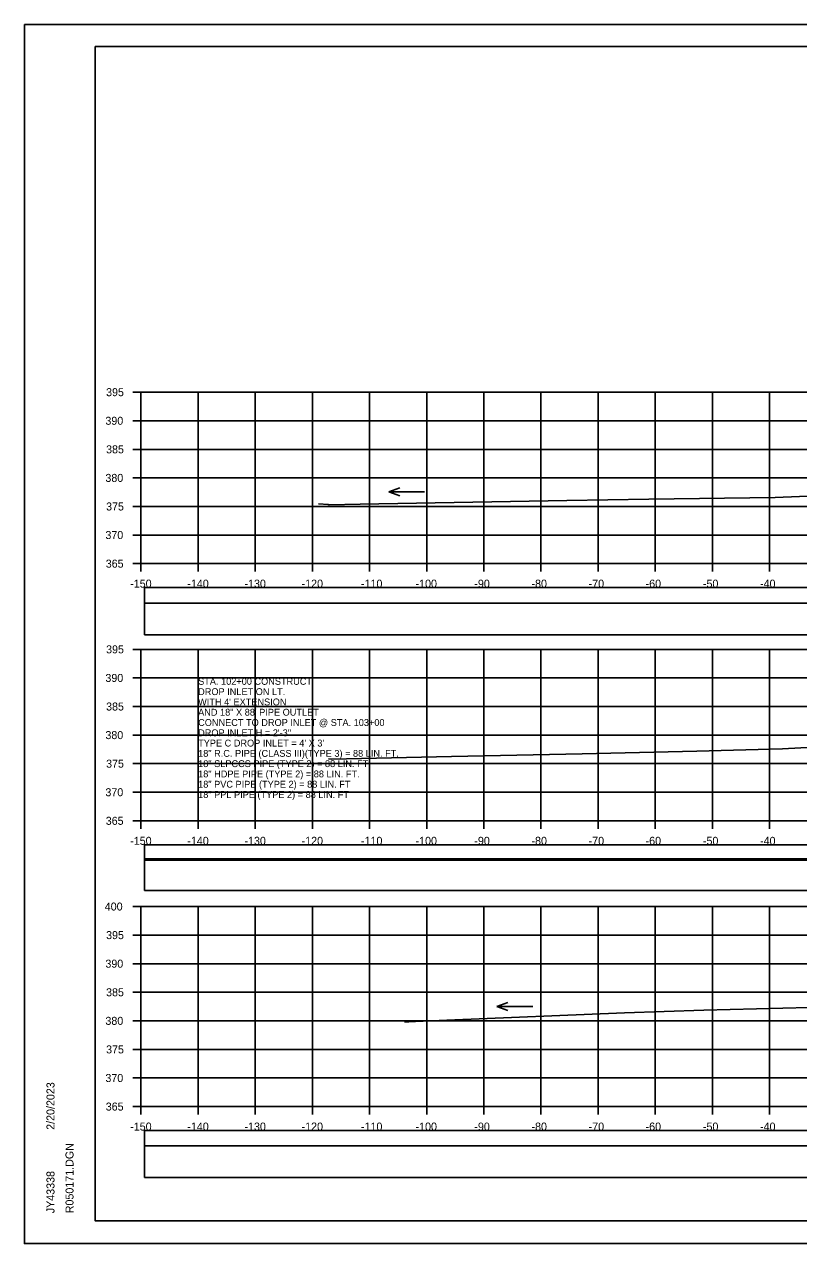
# Model space of a CAD drawing. Extents: x -37291014 to -37290680, y -936053 to -933067.
# Drawn here: x -37291013.5 to -37290878, y -935626.6 to -935413.3 of the extents above; entities that cross this region are included whole.
import ezdxf

# ---------------------------------------------------------------- set-up
doc = ezdxf.new("R2010")
doc.units = 0
for name, color, linetype in [('Default', 7, 'Continuous'), ('R_Axis', 7, 'Continuous'), ('R_Axis Annot', 7, 'Continuous'), ('R_Border', 7, 'Continuous'), ('R_Exist Surface', 7, 'Continuous'), ('R_Grid', 7, 'Continuous'), ('R_No Plot', 7, 'Continuous'), ('R_Water Annot', 7, 'Continuous')]:
    doc.layers.add(name, color=color, linetype=linetype)

msp = doc.modelspace()

# ---------------------------------------------------------------- linework, layer by layer
at = {"layer": 'Default'}
for points in [[(-37290992.48, -935514.55), (-37290693.72, -935514.55), (-37290693.72, -935511.85), (-37290992.48, -935511.85)], [(-37290992.48, -935520.08), (-37290693.72, -935520.08), (-37290693.72, -935514.55), (-37290992.48, -935514.55)], [(-37290992.48, -935559.55), (-37290693.72, -935559.55), (-37290693.72, -935556.85), (-37290992.48, -935556.85)], [(-37290992.48, -935564.82), (-37290693.72, -935564.82), (-37290693.72, -935559.3), (-37290992.48, -935559.3)], [(-37290992.48, -935609.55), (-37290693.72, -935609.55), (-37290693.72, -935606.85), (-37290992.48, -935606.85)], [(-37290992.48, -935615.08), (-37290693.72, -935615.08), (-37290693.72, -935609.55), (-37290992.48, -935609.55)]]:
    msp.add_lwpolyline(points, close=True, dxfattribs=at)
at = {"layer": 'R_Axis'}
for p, q in [((-37290994.5, -935477.65), (-37290993.1, -935477.65)), ((-37290993.1, -935507.65), (-37290993.1, -935477.65)), ((-37290994.5, -935482.65), (-37290993.1, -935482.65)), ((-37290994.5, -935487.65), (-37290993.1, -935487.65)), ((-37290994.5, -935492.65), (-37290993.1, -935492.65)), ((-37290994.5, -935497.65), (-37290993.1, -935497.65)), ((-37290994.5, -935502.65), (-37290993.1, -935502.65)), ((-37290994.5, -935507.65), (-37290993.1, -935507.65)), ((-37290993.1, -935507.65), (-37290693.1, -935507.65)), ((-37290993.1, -935509.05), (-37290993.1, -935507.65)), ((-37290983.1, -935509.05), (-37290983.1, -935507.65)), ((-37290973.1, -935509.05), (-37290973.1, -935507.65)), ((-37290963.1, -935509.05), (-37290963.1, -935507.65)), ((-37290953.1, -935509.05), (-37290953.1, -935507.65)), ((-37290943.1, -935509.05), (-37290943.1, -935507.65)), ((-37290933.1, -935509.05), (-37290933.1, -935507.65)), ((-37290923.1, -935509.05), (-37290923.1, -935507.65)), ((-37290913.1, -935509.05), (-37290913.1, -935507.65)), ((-37290903.1, -935509.05), (-37290903.1, -935507.65)), ((-37290893.1, -935509.05), (-37290893.1, -935507.65)), ((-37290883.1, -935509.05), (-37290883.1, -935507.65)), ((-37290994.5, -935522.65), (-37290993.1, -935522.65)), ((-37290993.1, -935552.65), (-37290993.1, -935522.65)), ((-37290994.5, -935527.65), (-37290993.1, -935527.65)), ((-37290994.5, -935532.65), (-37290993.1, -935532.65)), ((-37290994.5, -935537.65), (-37290993.1, -935537.65)), ((-37290994.5, -935542.65), (-37290993.1, -935542.65)), ((-37290994.5, -935547.65), (-37290993.1, -935547.65)), ((-37290994.5, -935552.65), (-37290993.1, -935552.65)), ((-37290993.1, -935552.65), (-37290693.1, -935552.65)), ((-37290993.1, -935554.05), (-37290993.1, -935552.65)), ((-37290983.1, -935554.05), (-37290983.1, -935552.65)), ((-37290973.1, -935554.05), (-37290973.1, -935552.65)), ((-37290963.1, -935554.05), (-37290963.1, -935552.65)), ((-37290953.1, -935554.05), (-37290953.1, -935552.65)), ((-37290943.1, -935554.05), (-37290943.1, -935552.65)), ((-37290933.1, -935554.05), (-37290933.1, -935552.65)), ((-37290923.1, -935554.05), (-37290923.1, -935552.65)), ((-37290913.1, -935554.05), (-37290913.1, -935552.65)), ((-37290903.1, -935554.05), (-37290903.1, -935552.65)), ((-37290893.1, -935554.05), (-37290893.1, -935552.65)), ((-37290883.1, -935554.05), (-37290883.1, -935552.65)), ((-37290994.5, -935567.65), (-37290993.1, -935567.65)), ((-37290993.1, -935602.65), (-37290993.1, -935567.65)), ((-37290994.5, -935572.65), (-37290993.1, -935572.65)), ((-37290994.5, -935577.65), (-37290993.1, -935577.65)), ((-37290994.5, -935582.65), (-37290993.1, -935582.65)), ((-37290994.5, -935587.65), (-37290993.1, -935587.65)), ((-37290994.5, -935592.65), (-37290993.1, -935592.65)), ((-37290994.5, -935597.65), (-37290993.1, -935597.65)), ((-37290994.5, -935602.65), (-37290993.1, -935602.65)), ((-37290993.1, -935602.65), (-37290693.1, -935602.65)), ((-37290993.1, -935604.05), (-37290993.1, -935602.65)), ((-37290983.1, -935604.05), (-37290983.1, -935602.65)), ((-37290973.1, -935604.05), (-37290973.1, -935602.65)), ((-37290963.1, -935604.05), (-37290963.1, -935602.65)), ((-37290953.1, -935604.05), (-37290953.1, -935602.65)), ((-37290943.1, -935604.05), (-37290943.1, -935602.65)), ((-37290933.1, -935604.05), (-37290933.1, -935602.65)), ((-37290923.1, -935604.05), (-37290923.1, -935602.65)), ((-37290913.1, -935604.05), (-37290913.1, -935602.65)), ((-37290903.1, -935604.05), (-37290903.1, -935602.65)), ((-37290893.1, -935604.05), (-37290893.1, -935602.65)), ((-37290883.1, -935604.05), (-37290883.1, -935602.65))]:
    msp.add_line(p, q, dxfattribs=at)
at = {"layer": 'R_Border'}
for p, q in [((-37291001.1, -935417.19), (-37290684.92, -935417.19)), ((-37291001.1, -935622.65), (-37291001.1, -935417.19)), ((-37291001.1, -935622.65), (-37291001.1, -935622.65)), ((-37290684.92, -935622.65), (-37291001.1, -935622.65))]:
    msp.add_line(p, q, dxfattribs=at)
at = {"layer": 'R_Exist Surface'}
for points in [[(-37290962.06, -935497.17), (-37290960.32, -935497.32), (-37290960.16, -935497.34), (-37290954.75, -935497.25), (-37290918.58, -935496.63), (-37290904.25, -935496.37), (-37290882.1, -935496.08), (-37290873.62, -935495.73)], [(-37290960.29, -935541.81), (-37290959.75, -935541.86), (-37290938.77, -935541.41), (-37290915.9, -935540.92), (-37290895.8, -935540.48), (-37290880.83, -935540.03), (-37290873.33, -935539.66)], [(-37290947, -935587.82), (-37290946.95, -935587.84), (-37290946.86, -935587.84), (-37290946.68, -935587.84), (-37290946.2, -935587.82), (-37290945.08, -935587.77), (-37290939.6, -935587.54), (-37290908.47, -935586.22), (-37290894.59, -935585.8), (-37290871.54, -935585.19)]]:
    msp.add_lwpolyline(points, dxfattribs=at)
at = {"layer": 'R_Grid'}
for p, q in [((-37290993.1, -935477.65), (-37290693.1, -935477.65)), ((-37290993.1, -935507.65), (-37290993.1, -935477.65)), ((-37290983.1, -935507.65), (-37290983.1, -935477.65)), ((-37290973.1, -935507.65), (-37290973.1, -935477.65)), ((-37290963.1, -935507.65), (-37290963.1, -935477.65)), ((-37290953.1, -935507.65), (-37290953.1, -935477.65)), ((-37290943.1, -935507.65), (-37290943.1, -935477.65)), ((-37290933.1, -935507.65), (-37290933.1, -935477.65)), ((-37290923.1, -935507.65), (-37290923.1, -935477.65)), ((-37290913.1, -935507.65), (-37290913.1, -935477.65)), ((-37290903.1, -935507.65), (-37290903.1, -935477.65)), ((-37290893.1, -935507.65), (-37290893.1, -935477.65)), ((-37290883.1, -935507.65), (-37290883.1, -935477.65)), ((-37290993.1, -935482.65), (-37290693.1, -935482.65)), ((-37290993.1, -935487.65), (-37290693.1, -935487.65)), ((-37290993.1, -935492.65), (-37290693.1, -935492.65)), ((-37290993.1, -935497.65), (-37290693.1, -935497.65)), ((-37290993.1, -935502.65), (-37290693.1, -935502.65)), ((-37290993.1, -935507.65), (-37290693.1, -935507.65)), ((-37290993.1, -935522.65), (-37290693.1, -935522.65)), ((-37290993.1, -935552.65), (-37290993.1, -935522.65)), ((-37290983.1, -935552.65), (-37290983.1, -935522.65)), ((-37290973.1, -935552.65), (-37290973.1, -935522.65)), ((-37290963.1, -935552.65), (-37290963.1, -935522.65)), ((-37290953.1, -935552.65), (-37290953.1, -935522.65)), ((-37290943.1, -935552.65), (-37290943.1, -935522.65)), ((-37290933.1, -935552.65), (-37290933.1, -935522.65)), ((-37290923.1, -935552.65), (-37290923.1, -935522.65)), ((-37290913.1, -935552.65), (-37290913.1, -935522.65)), ((-37290903.1, -935552.65), (-37290903.1, -935522.65)), ((-37290893.1, -935552.65), (-37290893.1, -935522.65)), ((-37290883.1, -935552.65), (-37290883.1, -935522.65)), ((-37290993.1, -935527.65), (-37290693.1, -935527.65)), ((-37290993.1, -935532.65), (-37290693.1, -935532.65)), ((-37290993.1, -935537.65), (-37290693.1, -935537.65)), ((-37290993.1, -935542.65), (-37290693.1, -935542.65)), ((-37290993.1, -935547.65), (-37290693.1, -935547.65)), ((-37290993.1, -935552.65), (-37290693.1, -935552.65)), ((-37290993.1, -935567.65), (-37290693.1, -935567.65)), ((-37290993.1, -935602.65), (-37290993.1, -935567.65)), ((-37290983.1, -935602.65), (-37290983.1, -935567.65)), ((-37290973.1, -935602.65), (-37290973.1, -935567.65)), ((-37290963.1, -935602.65), (-37290963.1, -935567.65)), ((-37290953.1, -935602.65), (-37290953.1, -935567.65)), ((-37290943.1, -935602.65), (-37290943.1, -935567.65)), ((-37290933.1, -935602.65), (-37290933.1, -935567.65)), ((-37290923.1, -935602.65), (-37290923.1, -935567.65)), ((-37290913.1, -935602.65), (-37290913.1, -935567.65)), ((-37290903.1, -935602.65), (-37290903.1, -935567.65)), ((-37290893.1, -935602.65), (-37290893.1, -935567.65)), ((-37290883.1, -935602.65), (-37290883.1, -935567.65)), ((-37290993.1, -935572.65), (-37290693.1, -935572.65)), ((-37290993.1, -935577.65), (-37290693.1, -935577.65)), ((-37290993.1, -935582.65), (-37290693.1, -935582.65)), ((-37290993.1, -935587.65), (-37290693.1, -935587.65)), ((-37290993.1, -935592.65), (-37290693.1, -935592.65)), ((-37290993.1, -935597.65), (-37290693.1, -935597.65)), ((-37290993.1, -935602.65), (-37290693.1, -935602.65))]:
    msp.add_line(p, q, dxfattribs=at)
at = {"layer": 'R_No Plot'}
for p, q in [((-37291013.5, -935413.29), (-37290680.17, -935413.29)), ((-37291013.5, -935626.63), (-37290680.17, -935626.63))]:
    msp.add_line(p, q, dxfattribs=at)
for points in [[(-37291013.51, -935413.29), (-37290680.17, -935413.29), (-37290680.17, -935626.63), (-37291013.51, -935626.63)], [(-37290767.18, -935417.19), (-37290747.56, -935417.19), (-37290747.56, -935427.07), (-37290731.45, -935427.07), (-37290708.25, -935427.07), (-37290708.25, -935451.4), (-37290684.92, -935451.4), (-37290684.92, -935622.65), (-37291001.1, -935622.65), (-37291001.1, -935417.19)]]:
    msp.add_lwpolyline(points, close=True, dxfattribs=at)
at = {"layer": 'R_Water Annot'}
for p, q in [((-37290949.74, -935495.06), (-37290947.82, -935494.36)), ((-37290943.46, -935495.06), (-37290949.74, -935495.06)), ((-37290949.74, -935495.06), (-37290947.82, -935495.76)), ((-37290930.83, -935585.14), (-37290928.9, -935584.44)), ((-37290924.54, -935585.14), (-37290930.83, -935585.14)), ((-37290930.83, -935585.14), (-37290928.9, -935585.84))]:
    msp.add_line(p, q, dxfattribs=at)

# ---------------------------------------------------------------- texts
at = {"layer": 'R_Axis Annot'}
for s, p in [('395', (-37290999.21, -935478.35)), ('390', (-37290999.33, -935483.35)), ('385', (-37290999.21, -935488.35)), ('380', (-37290999.33, -935493.35)), ('375', (-37290999.21, -935498.35)), ('370', (-37290999.33, -935503.35)), ('365', (-37290999.27, -935508.35)), ('-150', (-37290994.99, -935511.85)), ('-140', (-37290984.99, -935511.85)), ('-130', (-37290974.99, -935511.85)), ('-120', (-37290964.99, -935511.85)), ('-110', (-37290954.6, -935511.85)), ('-100', (-37290945.05, -935511.85)), ('-90', (-37290934.76, -935511.85)), ('-80', (-37290924.76, -935511.85)), ('-70', (-37290914.76, -935511.85)), ('-60', (-37290904.79, -935511.85)), ('-50', (-37290894.76, -935511.85)), ('-40', (-37290884.76, -935511.85)), ('395', (-37290999.21, -935523.35)), ('390', (-37290999.33, -935528.35)), ('385', (-37290999.21, -935533.35)), ('380', (-37290999.33, -935538.35)), ('375', (-37290999.21, -935543.35)), ('370', (-37290999.33, -935548.35)), ('365', (-37290999.27, -935553.35)), ('-150', (-37290994.99, -935556.85)), ('-140', (-37290984.99, -935556.85)), ('-130', (-37290974.99, -935556.85)), ('-120', (-37290964.99, -935556.85)), ('-110', (-37290954.6, -935556.85)), ('-100', (-37290945.05, -935556.85)), ('-90', (-37290934.76, -935556.85)), ('-80', (-37290924.76, -935556.85)), ('-70', (-37290914.76, -935556.85)), ('-60', (-37290904.79, -935556.85)), ('-50', (-37290894.76, -935556.85)), ('-40', (-37290884.76, -935556.85)), ('400', (-37290999.44, -935568.35)), ('395', (-37290999.21, -935573.35)), ('390', (-37290999.33, -935578.35)), ('385', (-37290999.21, -935583.35)), ('380', (-37290999.33, -935588.35)), ('375', (-37290999.21, -935593.35)), ('370', (-37290999.33, -935598.35)), ('365', (-37290999.27, -935603.35)), ('-150', (-37290994.99, -935606.85)), ('-140', (-37290984.99, -935606.85)), ('-130', (-37290974.99, -935606.85)), ('-120', (-37290964.99, -935606.85)), ('-110', (-37290954.6, -935606.85)), ('-100', (-37290945.05, -935606.85)), ('-90', (-37290934.76, -935606.85)), ('-80', (-37290924.76, -935606.85)), ('-70', (-37290914.76, -935606.85)), ('-60', (-37290904.79, -935606.85)), ('-50', (-37290894.76, -935606.85)), ('-40', (-37290884.76, -935606.85))]:
    msp.add_text(s, height=1.4, dxfattribs=at).set_placement(p)
at = {"layer": 'R_Border'}
for s, p in [('2/20/2023', (-37291008.24, -935606.72)), ('R050171.DGN', (-37291004.91, -935621.32)), ('JY43338', (-37291008.24, -935621.32))]:
    msp.add_text(s, height=1.4, rotation=90, dxfattribs=at).set_placement(p)
at = {"layer": 'R_Water Annot'}
for s, p in [('STA. 102+00 CONSTRUCT', (-37290983.1, -935528.85)), ('DROP INLET ON LT.', (-37290983.1, -935530.65)), ("WITH 4' EXTENSION", (-37290983.1, -935532.45)), ('AND 18" X 88\' PIPE OUTLET', (-37290983.1, -935534.25)), ('CONNECT TO DROP INLET @ STA. 103+00', (-37290983.1, -935536.05)), ('DROP INLET H = 2\'-3"', (-37290983.1, -935537.85)), ("TYPE C DROP INLET = 4' X 3'", (-37290983.1, -935539.65)), ('18" R.C. PIPE (CLASS III)(TYPE 3) = 88 LIN. FT.', (-37290983.1, -935541.45)), ('18" SLPCCS PIPE (TYPE 2) = 88 LIN. FT.', (-37290983.1, -935543.25)), ('18" HDPE PIPE (TYPE 2) = 88 LIN. FT.', (-37290983.1, -935545.05)), ('18" PVC PIPE (TYPE 2) = 88 LIN. FT', (-37290983.1, -935546.85)), ('18" PPL PIPE (TYPE 2) = 88 LIN. FT', (-37290983.1, -935548.65))]:
    msp.add_text(s, height=1.2, dxfattribs=at).set_placement(p)

doc.saveas('drawing.dxf')
